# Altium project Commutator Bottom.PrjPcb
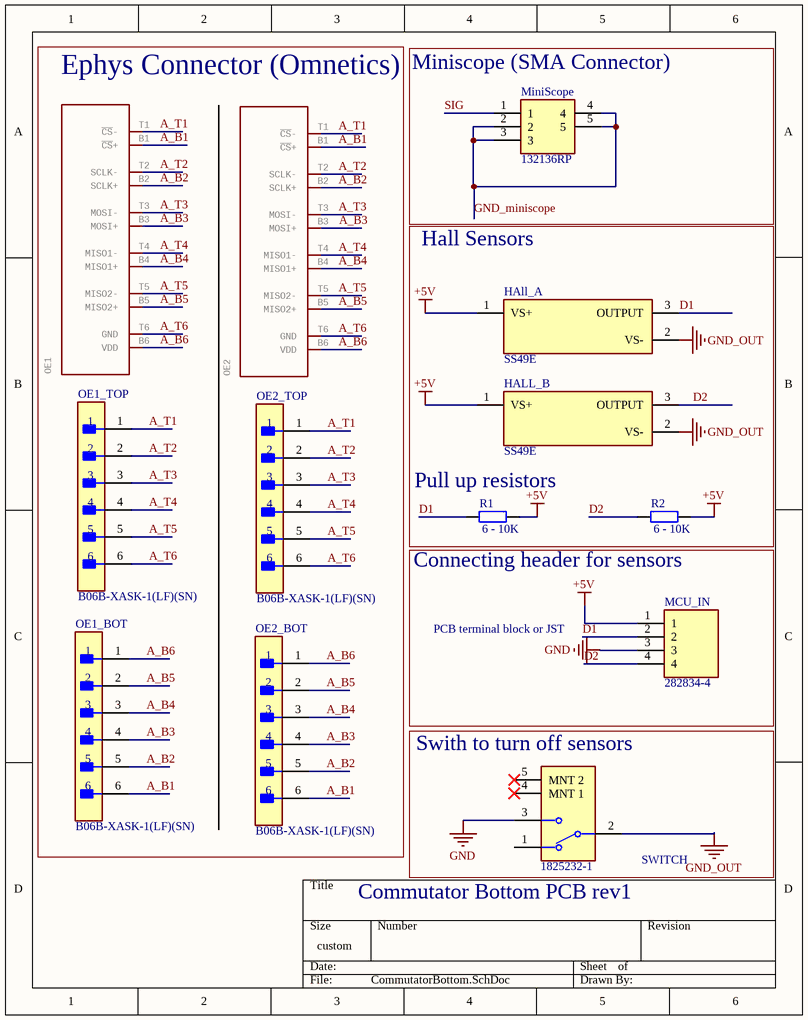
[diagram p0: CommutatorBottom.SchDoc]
1 sheet, 13 parts. Net scope: global (net labels, ports and power ports of the same name join across sheets).
Board file: Commutator_Bottom_V1.PcbDoc

## Sheet CommutatorBottom.SchDoc
size 149 x 190 mm; SheetNumber: 1; SheetTotal: 1

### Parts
HAll_A  SS49E  [FP-SS49E-MFG]
HALL_B  SS49E  [FP-SS49E-MFG]
MCU_IN  282834-4  [2828344]
MiniScope  132136RP  [132136RP]
OE1  RHD2000-CABLE-DAQ-SIDE  [RHD2000_EVAL_BOARD_OMNETICS_PZN-12-AA]  (value not drawn)
OE1_BOT  B06B-XASK-1(LF)(SN)  [FP-B06B-XASK-1_LF_SN-MFG]
OE1_TOP  B06B-XASK-1(LF)(SN)  [FP-B06B-XASK-1_LF_SN-MFG]
OE2  RHD2000-CABLE-DAQ-SIDE  [RHD2000_EVAL_BOARD_OMNETICS_PZN-12-AA]  (value not drawn)
OE2_BOT  B06B-XASK-1(LF)(SN)  [FP-B06B-XASK-1_LF_SN-MFG]
OE2_TOP  B06B-XASK-1(LF)(SN)  [FP-B06B-XASK-1_LF_SN-MFG]
R1  value 6 - 10K  [AXIAL-0.4]
R2  value 6 - 10K  [AXIAL-0.4]
SWITCH  1825232-1  [FP-1825232-1-MFG]

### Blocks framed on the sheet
Ephys Connector (Omnetics): OE1 OE1_BOT OE1_TOP OE2 OE2_BOT OE2_TOP
Miniscope (SMA Connector): MiniScope
Connecting header for sensors: MCU_IN
Swith to turn off sensors: SWITCH

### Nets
+5V: HAll_A.1(VS+) HALL_B.1(VS+) MCU_IN.1 R1.2 R2.2
GND: MCU_IN.3 SWITCH.3
GND_OUT: HAll_A.2(VS-) HALL_B.2(VS-) SWITCH.2
A_B1: OE1.B1(~{CS}+) OE1_BOT.6 OE2.B1(~{CS}+) OE2_BOT.6
A_B2: OE1.B2(SCLK+) OE1_BOT.5 OE2.B2(SCLK+) OE2_BOT.5
A_B3: OE1.B3(MOSI+) OE1_BOT.4 OE2.B3(MOSI+) OE2_BOT.4
A_B4: OE1.B4(MISO1+) OE1_BOT.3 OE2.B4(MISO1+) OE2_BOT.3
A_B5: OE1.B5(MISO2+) OE1_BOT.2 OE2.B5(MISO2+) OE2_BOT.2
A_B6: OE1.B6(VDD) OE1_BOT.1 OE2.B6(VDD) OE2_BOT.1
A_T1: OE1.T1(~{CS}-) OE1_TOP.1 OE2.T1(~{CS}-) OE2_TOP.1
A_T2: OE1.T2(SCLK-) OE1_TOP.2 OE2.T2(SCLK-) OE2_TOP.2
A_T3: OE1.T3(MOSI-) OE1_TOP.3 OE2.T3(MOSI-) OE2_TOP.3
A_T4: OE1.T4(MISO1-) OE1_TOP.4 OE2.T4(MISO1-) OE2_TOP.4
A_T5: OE1.T5(MISO2-) OE1_TOP.5 OE2.T5(MISO2-) OE2_TOP.5
A_T6: OE1.T6(GND) OE1_TOP.6 OE2.T6(GND) OE2_TOP.6
D1: HAll_A.3(OUTPUT) MCU_IN.2 R1.1
D2: HALL_B.3(OUTPUT) MCU_IN.4 R2.1
GND_miniscope: MiniScope.2 MiniScope.3 MiniScope.4 MiniScope.5
SIG: MiniScope.1

Not connected (* = marked no-connect by the designer): SWITCH 1 4(MNT_1)* 5(MNT_2)*

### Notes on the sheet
- Hall Sensors
- Pull up resistors
- PCB terminal block or JST
- (near SWITCH) Commutator Bottom PCB rev1

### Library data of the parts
HAll_A HALL_B = CMP-11168-000005-1: SENSOR LINEAR ANALOG RADIAL; Min Supply Voltage: 2.7V; Switching Current: 1.5mA; Input Current: 10mA; Min Supply Voltage (DC): 4V; Max Supply Voltage: 6.5V; Operating Supply Current: 6mA; Output Voltage: 1.75mV; Max Supply Voltage (DC): 10V; Leakage Current: 10uA; Response Time: 3us
MCU_IN = 282834-4: Connector; Manufacturer_Name: TE Connectivity
MiniScope = 132136RP: Connector; Manufacturer_Name: Amphenol
OE1 OE2 = RHD2000-CABLE-DAQ-SIDE: Omnetics PZN-12-AA RHD2000 socket - DAQ side; GateName_1: A
OE1_BOT OE1_TOP OE2_BOT OE2_TOP = CMP-17439-000268-1: CONN HEADER VERT 6POS 2.5MM; Voltage Rating: 250V; Contact Resistance: 20mR; Number of Poles: 6; Current Rating: 3A; Insulation Resistance: 1GR; Mated Stacking Heights: 11.3mm; Lead Length: 3.4mm; Gender: Male; Wire/Cable Gauge: 20AWG
R1 R2 = Res2: Resistor
SWITCH = CMP-03405-000001-1: SWITCH SLIDE SPDT 200MA 30V; Manufacturer: TE Connectivity; Contact Current Rating: 0.2A; Contact Resistance: 20mΩ; Electromechanical Life: 10000Cycles; Operating Force: 200gf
